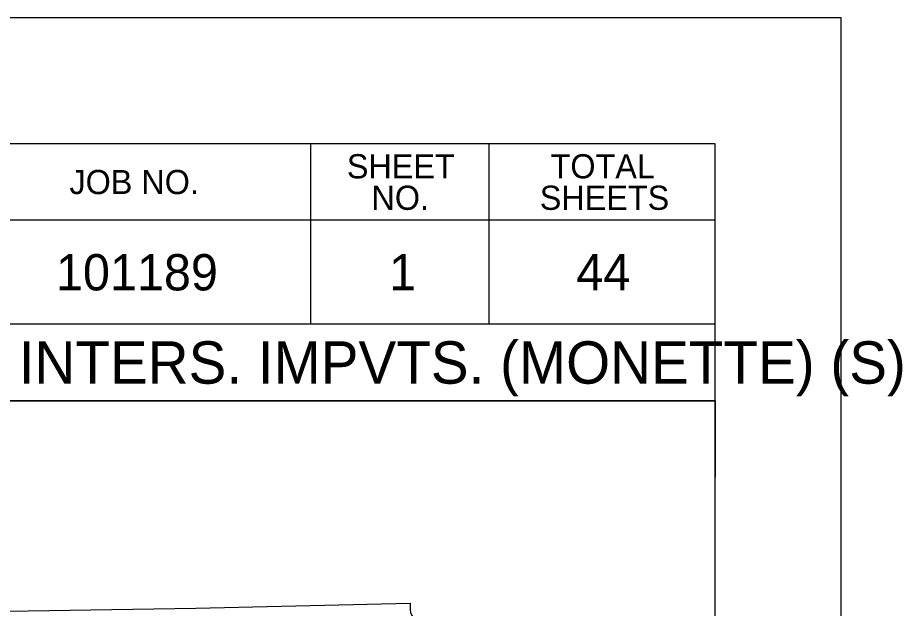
# Model space of a CAD drawing. Extents: x -0.54 to 1.64, y 0 to 0.92.
# Drawn here: x 1.2805 to 1.4268, y 0.8191 to 0.9167 of the extents above; entities that cross this region are included whole.
import ezdxf

# ---------------------------------------------------------------- set-up
doc = ezdxf.new("R2010")
doc.units = 0
for name, color, linetype in [('SHET_Annotations', 7, 'Continuous'), ('SHET_Border-Lines', 7, 'Continuous'), ('SHET_Border-Text', 7, 'Continuous')]:
    doc.layers.add(name, color=color, linetype=linetype)

msp = doc.modelspace()

# ---------------------------------------------------------------- linework, layer by layer
at = {"layer": 'SHET_Annotations'}
msp.add_lwpolyline([(1.09511, 0.81784), (1.16886, 0.81779), (1.23365, 0.81792), (1.31002, 0.81909), (1.34545, 0.81992)], dxfattribs=at)
msp.add_spline([(1.34545, 0.81992), (1.34568, 0.81792), (1.3463, 0.81688), (1.34641, 0.81496), (1.34719, 0.81413), (1.34851, 0.81333), (1.34968, 0.81198), (1.34994, 0.81042), (1.34957, 0.80884), (1.34949, 0.80708), (1.34931, 0.80552), (1.34905, 0.8041), (1.34794, 0.80295), (1.3469, 0.80215), (1.34594, 0.80119), (1.34527, 0.80015), (1.34405, 0.79906), (1.34288, 0.79792), (1.34192, 0.79691), (1.34099, 0.79564), (1.3405, 0.79424), (1.33948, 0.79323), (1.33865, 0.79232), (1.33754, 0.7911), (1.33699, 0.78983), (1.33596, 0.78846), (1.3357, 0.78708), (1.33448, 0.78431)], degree=3, dxfattribs=at)
at = {"layer": 'SHET_Border-Lines'}
for p, q in [((1.32894, 0.89583), (1.32894, 0.86601)), ((1.35843, 0.89583), (1.35843, 0.86601)), ((1.39583, 0.88329), (1.39583, 0.88329)), ((1.39583, 0.8832), (1.21266, 0.8832)), ((1.39583, 0.86601), (1.21266, 0.86601)), ((1.39583, 0.85338), (1.21266, 0.85338))]:
    msp.add_line(p, q, dxfattribs=at)
for points in [[(0, 0), (1.41667, 0), (1.41667, 0.91667), (0, 0.91667)], [(0.04167, 0.02083), (1.39583, 0.02083), (1.39583, 0.89583), (0.04167, 0.89583)]]:
    msp.add_lwpolyline(points, close=True, dxfattribs=at)
msp.add_lwpolyline([(1.12962, 0.85338), (1.21266, 0.85338), (1.39583, 0.85338), (1.39583, 0.84075), (1.39583, 0.89583), (1.12962, 0.89583)], dxfattribs=at)

# ---------------------------------------------------------------- texts
at = {"layer": 'SHET_Annotations'}
for s, height, p in [('101189', 0.006, (1.28687, 0.87161)), ('1', 0.006, (1.34195, 0.87161)), ('44', 0.006, (1.3729, 0.87165)), ('HWYS. 18/139 INTERS. IMPVTS. (MONETTE) (S)', 0.007, (1.2162, 0.8562))]:
    msp.add_text(s, height=height, dxfattribs=at).set_placement(p)
at = {"layer": 'SHET_Border-Text'}
for s, p in [('SHEET', (1.33496, 0.89012)), ('TOTAL', (1.36864, 0.89012)), ('JOB NO.', (1.2891, 0.88752)), ('NO.', (1.33903, 0.88492)), ('SHEETS', (1.36685, 0.88492))]:
    msp.add_text(s, height=0.004, dxfattribs=at).set_placement(p)

doc.saveas('drawing.dxf')
